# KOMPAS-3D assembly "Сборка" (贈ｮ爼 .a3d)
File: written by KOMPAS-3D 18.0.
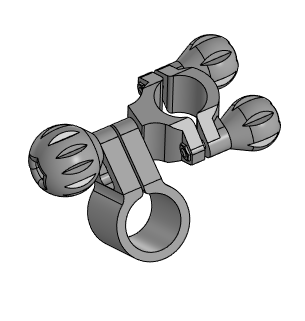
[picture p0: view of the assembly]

Document properties: Автор: Пользователь Windows; Полное имя файла: F:\Модели\Мех детали\Велосипед\Крепление фонаря\2\Сборка.a3d

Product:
- Part/product: Сборка
    Масса: 0.446413
  - Component [standard]: Болт М5-6gx40 ГОСТ 7805-70  | Масса: 0.007456; Раздел спецификации: Стандартные изделия; Рассекать на разрезах: no
  - Component [standard]: Болт М4-6gx30 ГОСТ 7805-70  | qty 2  | Масса: 0.00375; Раздел спецификации: Стандартные изделия; Рассекать на разрезах: no
  - Component [standard]: Гайка М5-6H ГОСТ 5915-70  | Масса: 0.00144; Раздел спецификации: Стандартные изделия; Рассекать на разрезах: no
  - Component [standard]: Гайка М4-6H ГОСТ 5915-70  | qty 2  | Масса: 0.0008; Раздел спецификации: Стандартные изделия; Рассекать на разрезах: no
  - Component [detail]: Деталь  | Масса: 0.056758; source file: Крепление на руль.m3d
  - Component [detail]: Деталь  | Масса: 0.12994; source file: Крепление фонаря.m3d
  - Component [detail]: Деталь  | Масса: 0.0981276; source file: Накидная гайка М5х30.m3d
  - Component [detail]: Деталь  | Масса: 0.0529721; source file: Прижим на руль.m3d
  - Component [detail]: Деталь  | qty 2  | Масса: 0.0453094; source file: Накидная гайка М4х25.m3d

Referenced files in F:\Модели\Мех детали\Велосипед\Крепление фонаря\2\: Крепление на руль.m3d, Крепление фонаря.m3d, Накидная гайка М5х30.m3d, Прижим на руль.m3d, Накидная гайка М4х25.m3d
Referenced files in C:\Program Files\ASCON\KOMPAS-3D v18\Libs\PARTLib\DATA\vault\Methods\Kompas\3D\: PLib_Nut_OST92_900.m3d, PLib_Bolt_1_900.m3d
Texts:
  Деталь (1)
  Деталь (2)
  bcut1
  hole1
  hcut1
  hole2
  cut1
